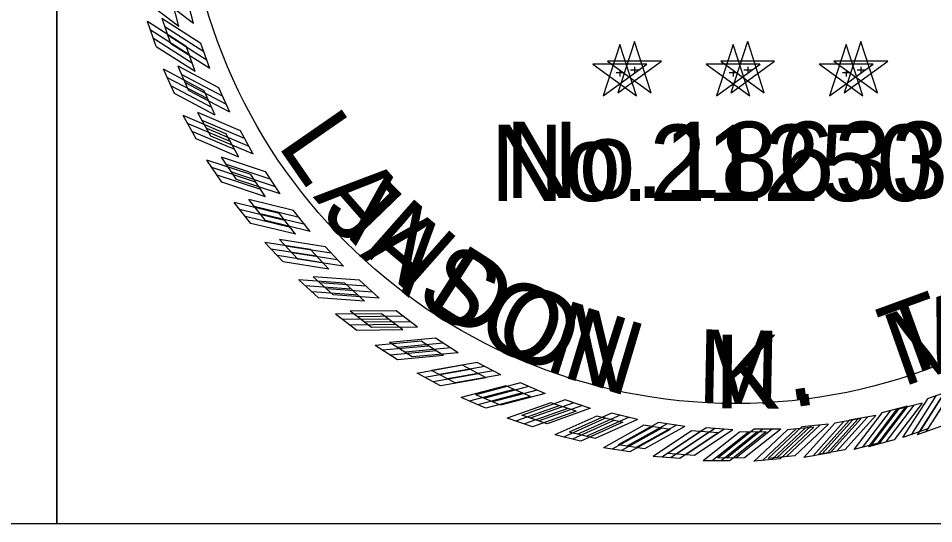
# Model space of a CAD drawing. Extents: x -2512 to 3792, y -435 to 2624.
# Drawn here: x 3002.5 to 3189.1, y 212.7 to 315.8 of the extents above; entities that cross this region are included whole.
import ezdxf

# ---------------------------------------------------------------- set-up
doc = ezdxf.new("R2010")
doc.units = 0
for name, color, linetype in [('G-ANNO-NPLT', 7, 'Continuous'), ('R_No Plot', 7, 'Continuous'), ('STAMP', 7, 'Continuous'), ('STAMP_LKM', 7, 'Continuous')]:
    doc.layers.add(name, color=color, linetype=linetype)

msp = doc.modelspace()

# ---------------------------------------------------------------- linework, layer by layer
at = {"layer": 'G-ANNO-NPLT'}
msp.add_circle((3148.72, 349.66), 112.43, dxfattribs=at)
at = {"layer": 'R_No Plot'}
for points in [[(2730.1, 488.67), (3010.37, 488.67), (3010.37, 212.74), (2730.1, 212.74)], [(3010.37, 488.67), (3290.65, 488.67), (3290.65, 212.74), (3010.37, 212.74)]]:
    msp.add_lwpolyline(points, close=True, dxfattribs=at)
at = {"layer": 'STAMP'}
for p, q in [((3035.24, 314.12), (3033.85, 319.39)), ((3030.63, 309.98), (3028.81, 315.11)), ((3038.56, 304.91), (3036.74, 310.05)), ((3125.11, 310.42), (3121.7, 299.98)), ((3128.5, 299.98), (3125.11, 310.43)), ((3148.19, 310.42), (3144.78, 299.98)), ((3151.58, 299.98), (3148.19, 310.43)), ((3171.26, 310.42), (3167.86, 299.98)), ((3174.65, 299.98), (3171.27, 310.43)), ((3130.59, 306.43), (3119.61, 306.44)), ((3119.62, 306.43), (3128.5, 299.97)), ((3121.72, 299.98), (3130.61, 306.43)), ((3153.67, 306.43), (3142.69, 306.44)), ((3142.7, 306.43), (3151.58, 299.97)), ((3144.79, 299.98), (3153.69, 306.43)), ((3176.75, 306.43), (3165.77, 306.44)), ((3165.78, 306.43), (3174.66, 299.97)), ((3167.87, 299.98), (3176.76, 306.43)), ((3034.31, 300.41), (3032.07, 305.37)), ((3124.33, 304.68), (3125.96, 304.68)), ((3125.12, 305.26), (3125.12, 303.89)), ((3147.4, 304.68), (3149.04, 304.68)), ((3148.2, 305.26), (3148.2, 303.89)), ((3170.48, 304.68), (3172.11, 304.68)), ((3171.27, 305.26), (3171.27, 303.89)), ((3042.63, 296.01), (3040.39, 300.98)), ((3038.76, 291.17), (3036.13, 295.93)), ((3047.42, 287.47), (3044.78, 292.25)), ((3043.97, 282.33), (3040.95, 286.86)), ((3052.9, 279.36), (3049.88, 283.9)), ((3049.88, 273.95), (3046.5, 278.22)), ((3059.03, 271.74), (3055.65, 276.01)), ((3056.47, 266.09), (3052.75, 270.06)), ((3065.77, 264.64), (3062.04, 268.62)), ((3063.69, 258.81), (3059.65, 262.45)), ((3073.08, 258.12), (3069.03, 261.78)), ((3071.48, 252.14), (3067.16, 255.44)), ((3080.89, 252.23), (3076.56, 255.54)), ((3079.8, 246.14), (3075.21, 249.07)), ((3089.17, 247.01), (3084.58, 249.95)), ((3097.85, 242.48), (3093.03, 245.04)), ((3088.58, 240.84), (3083.77, 243.39)), ((3106.87, 238.69), (3101.86, 240.84)), ((3192.96, 240.03), (3187.82, 238.22)), ((3097.77, 236.29), (3092.77, 238.43)), ((3116.18, 235.66), (3111.01, 237.38)), ((3183.75, 236.71), (3178.48, 235.33)), ((3107.31, 232.51), (3102.14, 234.23)), ((3125.7, 233.4), (3120.4, 234.69)), ((3174.3, 234.16), (3168.93, 233.22)), ((3135.38, 231.94), (3129.99, 232.79)), ((3145.15, 231.29), (3139.71, 231.69)), ((3154.93, 231.44), (3149.48, 231.39)), ((3164.67, 232.4), (3159.24, 231.9)), ((3187.89, 232.1), (3182.76, 230.29)), ((3117.12, 229.54), (3111.83, 230.82)), ((3127.15, 227.38), (3121.77, 228.23)), ((3178.04, 229.22), (3172.78, 227.84)), ((3137.32, 226.06), (3131.89, 226.46)), ((3157.81, 225.95), (3152.39, 225.46)), ((3168, 227.17), (3162.64, 226.23)), ((3147.56, 225.58), (3142.12, 225.53))]:
    msp.add_line(p, q, dxfattribs=at)
for points in [[(3035.24, 314.11), (3027.76, 319.82)], [(3036.74, 310.04), (3028.81, 315.11)], [(3037.33, 308.33), (3029.4, 313.4)], [(3038, 306.56), (3030.06, 311.63)], [(3038.57, 304.9), (3030.63, 309.97)], [(3040.39, 300.97), (3032.07, 305.37)], [(3041.12, 299.31), (3032.8, 303.71)], [(3041.93, 297.61), (3033.61, 302)], [(3042.64, 296), (3034.31, 300.4)], [(3044.78, 292.24), (3036.12, 295.93)], [(3045.65, 290.64), (3036.99, 294.34)], [(3046.6, 289.01), (3037.94, 292.7)], [(3047.43, 287.47), (3038.77, 291.16)], [(3049.88, 283.89), (3040.94, 286.86)], [(3050.87, 282.38), (3041.94, 285.34)], [(3051.95, 280.83), (3043.02, 283.79)], [(3052.91, 279.36), (3043.98, 282.33)], [(3055.65, 276), (3046.5, 278.22)], [(3056.76, 274.57), (3047.61, 276.79)], [(3057.97, 273.12), (3048.82, 275.33)], [(3059.04, 271.73), (3049.89, 273.95)], [(3062.05, 268.61), (3052.74, 270.06)], [(3063.27, 267.28), (3053.97, 268.73)], [(3064.6, 265.93), (3055.3, 267.38)], [(3065.78, 264.64), (3056.48, 266.09)], [(3069.03, 261.77), (3059.64, 262.45)], [(3070.37, 260.54), (3060.98, 261.23)], [(3071.8, 259.31), (3062.41, 259.99)], [(3073.09, 258.12), (3063.7, 258.8)], [(3076.56, 255.54), (3067.15, 255.44)], [(3077.99, 254.42), (3068.58, 254.33)], [(3079.52, 253.31), (3070.11, 253.21)], [(3080.9, 252.23), (3071.49, 252.14)], [(3084.58, 249.94), (3075.21, 249.07)], [(3086.1, 248.95), (3076.73, 248.08)], [(3087.71, 247.97), (3078.34, 247.09)], [(3089.18, 247.01), (3079.81, 246.14)], [(3093.03, 245.03), (3083.76, 243.38)], [(3094.63, 244.17), (3085.36, 242.52)], [(3096.32, 243.32), (3087.05, 241.67)], [(3097.86, 242.49), (3088.59, 240.84)], [(3101.86, 240.83), (3092.76, 238.43)], [(3103.52, 240.1), (3094.42, 237.7)], [(3105.28, 239.4), (3096.18, 236.99)], [(3191.31, 239.47), (3186.24, 231.54)], [(3192.96, 240.04), (3187.89, 232.11)], [(3106.88, 238.69), (3097.78, 236.29)], [(3111.01, 237.38), (3102.14, 234.23)], [(3187.82, 238.22), (3182.75, 230.28)], [(3189.54, 238.8), (3184.47, 230.87)], [(3112.72, 236.79), (3103.85, 233.64)], [(3114.53, 236.23), (3105.66, 233.08)], [(3116.19, 235.66), (3107.31, 232.51)], [(3178.48, 235.32), (3172.78, 227.84)], [(3180.24, 235.77), (3174.53, 228.28)], [(3182.06, 236.29), (3176.35, 228.8)], [(3183.76, 236.72), (3178.05, 229.23)], [(3120.41, 234.69), (3111.83, 230.82)], [(3122.17, 234.24), (3113.59, 230.38)], [(3124.01, 233.84), (3115.43, 229.97)], [(3125.71, 233.41), (3117.13, 229.54)], [(3170.73, 233.51), (3164.42, 226.52)], [(3172.58, 233.88), (3166.27, 226.89)], [(3174.31, 234.17), (3168, 227.18)], [(3130, 232.79), (3121.77, 228.22)], [(3131.79, 232.49), (3123.55, 227.92)], [(3133.66, 232.24), (3125.43, 227.67)], [(3135.39, 231.95), (3127.16, 227.38)], [(3139.71, 231.68), (3131.89, 226.46)], [(3141.52, 231.53), (3133.69, 226.31)], [(3143.41, 231.44), (3135.58, 226.21)], [(3149.49, 231.39), (3142.12, 225.53)], [(3151.3, 231.39), (3143.93, 225.53)], [(3153.19, 231.45), (3145.82, 225.59)], [(3154.94, 231.45), (3147.57, 225.59)], [(3159.25, 231.9), (3152.39, 225.45)], [(3161.06, 232.05), (3154.2, 225.6)], [(3162.93, 232.26), (3156.07, 225.82)], [(3164.68, 232.41), (3157.82, 225.96)], [(3168.94, 233.21), (3162.63, 226.22)], [(3145.15, 231.29), (3137.33, 226.06)]]:
    msp.add_lwpolyline(points, dxfattribs=at)
at = {"layer": 'STAMP_LKM'}
for p, q in [((3038.22, 314.71), (3036.83, 319.98)), ((3033.6, 310.57), (3031.79, 315.7)), ((3041.54, 305.5), (3039.72, 310.64)), ((3128.08, 311.01), (3124.68, 300.57)), ((3131.48, 300.58), (3128.09, 311.03)), ((3151.16, 311.01), (3147.76, 300.57)), ((3154.55, 300.58), (3151.17, 311.03)), ((3174.24, 311.01), (3170.84, 300.57)), ((3177.63, 300.58), (3174.25, 311.03)), ((3133.57, 307.03), (3122.59, 307.04)), ((3122.6, 307.03), (3131.48, 300.56)), ((3124.69, 300.58), (3133.59, 307.02)), ((3156.65, 307.03), (3145.67, 307.04)), ((3145.68, 307.03), (3154.56, 300.56)), ((3147.77, 300.58), (3156.66, 307.02)), ((3179.73, 307.03), (3168.74, 307.04)), ((3168.75, 307.03), (3177.63, 300.56)), ((3170.85, 300.58), (3179.74, 307.02)), ((3037.28, 301), (3035.05, 305.96)), ((3127.3, 305.27), (3128.94, 305.27)), ((3128.1, 305.86), (3128.1, 304.48)), ((3150.38, 305.27), (3152.01, 305.27)), ((3151.17, 305.86), (3151.17, 304.48)), ((3173.46, 305.27), (3175.09, 305.27)), ((3174.25, 305.86), (3174.25, 304.48)), ((3045.61, 296.6), (3043.37, 301.58)), ((3041.74, 291.76), (3039.11, 296.52)), ((3050.4, 288.07), (3047.76, 292.84)), ((3046.95, 282.93), (3043.93, 287.45)), ((3055.88, 279.96), (3052.86, 284.5)), ((3052.86, 274.55), (3049.48, 278.81)), ((3062.01, 272.33), (3058.62, 276.6)), ((3059.45, 266.69), (3055.73, 270.66)), ((3068.75, 265.23), (3065.02, 269.21)), ((3066.67, 259.4), (3062.63, 263.05)), ((3076.06, 258.72), (3072.01, 262.37)), ((3074.46, 252.73), (3070.13, 256.03)), ((3083.87, 252.83), (3079.54, 256.14)), ((3092.15, 247.6), (3087.56, 250.54)), ((3082.77, 246.73), (3078.19, 249.66)), ((3100.83, 243.08), (3096.01, 245.63)), ((3091.56, 241.44), (3086.75, 243.98)), ((3109.85, 239.29), (3104.84, 241.43)), ((3100.75, 236.88), (3095.75, 239.02)), ((3119.16, 236.25), (3113.98, 237.98)), ((3186.73, 237.31), (3181.45, 235.92)), ((3128.68, 234), (3123.38, 235.29)), ((3110.28, 233.11), (3105.12, 234.83)), ((3138.36, 232.54), (3132.97, 233.39)), ((3177.28, 234.76), (3171.91, 233.81)), ((3120.1, 230.13), (3114.81, 231.42)), ((3148.12, 231.88), (3142.69, 232.28)), ((3157.91, 232.04), (3152.46, 231.99)), ((3167.65, 233), (3162.22, 232.5)), ((3190.87, 232.7), (3185.74, 230.88)), ((3181.02, 229.82), (3175.76, 228.44)), ((3130.12, 227.97), (3124.75, 228.82)), ((3170.97, 227.77), (3165.61, 226.82)), ((3140.3, 226.65), (3134.87, 227.05)), ((3150.54, 226.18), (3145.1, 226.13)), ((3160.79, 226.55), (3155.37, 226.05))]:
    msp.add_line(p, q, dxfattribs=at)
for points in [[(3038.22, 314.71), (3030.73, 320.41)], [(3039.72, 310.64), (3031.78, 315.71)], [(3040.31, 308.92), (3032.37, 313.99)], [(3040.98, 307.16), (3033.04, 312.22)], [(3041.54, 305.5), (3033.61, 310.57)], [(3043.37, 301.57), (3035.05, 305.97)], [(3044.1, 299.91), (3035.77, 304.31)], [(3044.91, 298.2), (3036.59, 302.6)], [(3045.62, 296.6), (3037.29, 301)], [(3047.76, 292.83), (3039.1, 296.53)], [(3048.62, 291.24), (3039.96, 294.93)], [(3049.57, 289.61), (3040.92, 293.3)], [(3050.41, 288.07), (3041.75, 291.76)], [(3052.86, 284.49), (3043.92, 287.46)], [(3053.85, 282.97), (3044.91, 285.94)], [(3054.93, 281.42), (3046, 284.39)], [(3055.89, 279.96), (3046.95, 282.92)], [(3058.62, 276.6), (3049.47, 278.81)], [(3059.74, 275.16), (3050.59, 277.38)], [(3060.94, 273.71), (3051.8, 275.93)], [(3062.02, 272.33), (3052.87, 274.55)], [(3065.02, 269.2), (3055.72, 270.66)], [(3066.25, 267.87), (3056.95, 269.33)], [(3067.57, 266.52), (3058.27, 267.98)], [(3068.76, 265.23), (3059.46, 266.69)], [(3072.01, 262.37), (3062.62, 263.05)], [(3073.35, 261.14), (3063.96, 261.82)], [(3074.78, 259.9), (3065.39, 260.58)], [(3076.06, 258.72), (3066.67, 259.4)], [(3079.54, 256.13), (3070.13, 256.03)], [(3080.97, 255.02), (3071.56, 254.92)], [(3082.5, 253.9), (3073.09, 253.81)], [(3083.88, 252.83), (3074.47, 252.73)], [(3087.56, 250.54), (3078.19, 249.66)], [(3089.08, 249.54), (3079.7, 248.67)], [(3090.69, 248.56), (3081.32, 247.69)], [(3092.16, 247.6), (3082.78, 246.73)], [(3096.01, 245.62), (3086.74, 243.98)], [(3097.61, 244.76), (3088.34, 243.12)], [(3099.3, 243.91), (3090.03, 242.27)], [(3100.84, 243.08), (3091.57, 241.44)], [(3104.84, 241.43), (3095.74, 239.02)], [(3106.5, 240.7), (3097.4, 238.29)], [(3108.26, 239.99), (3099.15, 237.59)], [(3109.86, 239.29), (3100.76, 236.89)], [(3192.52, 239.4), (3187.45, 231.47)], [(3113.99, 237.97), (3105.12, 234.82)], [(3115.7, 237.38), (3106.83, 234.24)], [(3186.73, 237.31), (3181.03, 229.83)], [(3190.8, 238.81), (3185.73, 230.88)], [(3117.51, 236.83), (3108.64, 233.68)], [(3119.16, 236.26), (3110.29, 233.11)], [(3123.39, 235.28), (3114.81, 231.42)], [(3181.46, 235.92), (3175.76, 228.43)], [(3183.22, 236.36), (3177.51, 228.88)], [(3185.04, 236.88), (3179.33, 229.4)], [(3125.15, 234.84), (3116.56, 230.97)], [(3126.99, 234.43), (3118.41, 230.56)], [(3128.69, 234), (3120.11, 230.13)], [(3132.98, 233.38), (3124.74, 228.82)], [(3171.92, 233.81), (3165.61, 226.82)], [(3173.7, 234.11), (3167.4, 227.12)], [(3175.56, 234.48), (3169.25, 227.48)], [(3177.28, 234.76), (3170.98, 227.77)], [(3134.77, 233.08), (3126.53, 228.52)], [(3136.64, 232.83), (3128.41, 228.27)], [(3138.37, 232.54), (3130.13, 227.98)], [(3142.69, 232.28), (3134.86, 227.05)], [(3144.5, 232.13), (3136.67, 226.9)], [(3146.39, 232.03), (3138.56, 226.8)], [(3148.13, 231.89), (3140.3, 226.66)], [(3152.46, 231.98), (3145.09, 226.12)], [(3154.28, 231.98), (3146.91, 226.12)], [(3156.17, 232.04), (3148.8, 226.18)], [(3157.92, 232.04), (3150.55, 226.18)], [(3162.23, 232.49), (3155.37, 226.05)], [(3164.03, 232.64), (3157.17, 226.2)], [(3165.91, 232.86), (3159.05, 226.41)], [(3167.66, 233), (3160.8, 226.56)]]:
    msp.add_lwpolyline(points, dxfattribs=at)

# ---------------------------------------------------------------- texts
at = {"layer": 'STAMP'}
msp.add_text('No.21250', height=15.578, dxfattribs=at).set_placement((3098.69, 278.51))
for s, rotation, p in [('J', 314.0187, (3063.89, 275.64)), ('A', 319.8555, (3071.86, 267.4)), ('S', 327.1515, (3082.93, 258.31)), ('O', 334.4475, (3095.06, 250.69)), ('T', 20.0476, (3181.89, 242.07)), ('N', 342.4731, (3109.4, 244.17)), ('M', 358.8891, (3140.82, 237.35)), ('.', 8.3739, (3159.43, 237.59))]:
    msp.add_text(s, height=15.03, rotation=rotation, dxfattribs=at).set_placement(p)
at = {"layer": 'STAMP_LKM'}
for s, rotation, p in [('L', 304.7099, (3055.14, 289.95)), ('A', 311.2763, (3062.48, 279.34)), ('N', 318.5723, (3072, 268.63)), ('D', 327.3275, (3085.11, 257.51)), ('O', 335.3531, (3098.49, 249.17)), ('M', 19.494, (3182.68, 240.53)), ('N', 343.3787, (3112.9, 242.78)), ('K', 359.7948, (3144.38, 236.26)), ('.', 7.8204, (3160.15, 236.41))]:
    msp.add_text(s, height=15.03, rotation=rotation, dxfattribs=at).set_placement(p)
msp.add_text('No.18633', height=15.578, dxfattribs=at).set_placement((3101.67, 279.1))

doc.saveas('drawing.dxf')
